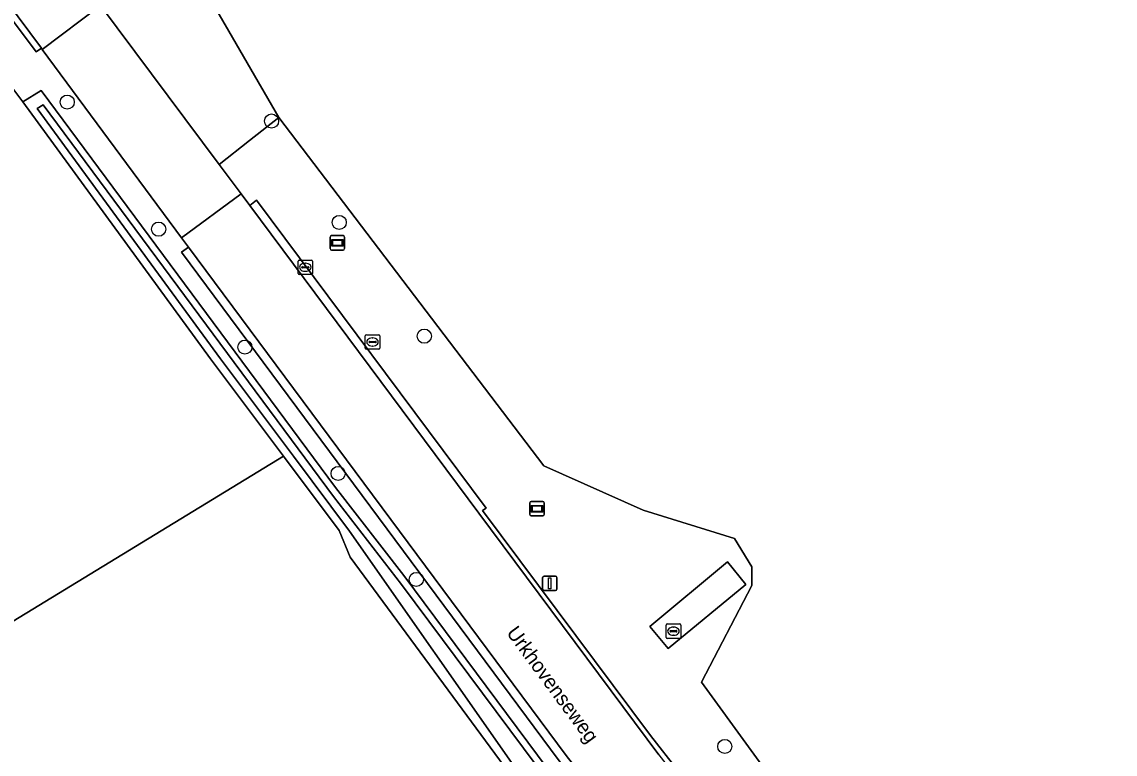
# Model space of a CAD drawing. Extents: x 164494 to 166241, y 382475 to 384495.
# Drawn here: x 165073.2 to 165148.9, y 383082.2 to 383132.9 of the extents above; entities that cross this region are included whole.
import ezdxf

# ---------------------------------------------------------------- set-up
doc = ezdxf.new("R2010")
doc.units = 0
for name, color, linetype in [('IMGEO_Berm_halfverhard', 7, 'Continuous'), ('IMGEO_Boom', 7, 'Continuous'), ('IMGEO_Bouwland', 7, 'Continuous'), ('IMGEO_Brandkraan', 7, 'Continuous'), ('IMGEO_Erf', 7, 'Continuous'), ('IMGEO_Grasland_agrarisch', 7, 'Continuous'), ('IMGEO_Grasland_overig', 7, 'Continuous'), ('IMGEO_Groenvoorziening', 7, 'Continuous'), ('IMGEO_Hek', 7, 'Continuous'), ('IMGEO_Oever', 7, 'Continuous'), ('IMGEO_Openbare_ruimte_label', 7, 'Continuous'), ('IMGEO_Rijbaan_lokaal_gesloten', 7, 'Continuous'), ('IMGEO_Verkeersbordpaal', 7, 'Continuous'), ('IMGEO_Verklikker', 7, 'Continuous'), ('IMGEO_Voetpad_open', 7, 'Continuous'), ('IMGEO_Waterloop', 7, 'Continuous')]:
    doc.layers.add(name, color=color, linetype=linetype)

msp = doc.modelspace()

# ---------------------------------------------------------------- linework, layer by layer
at = {"layer": 'IMGEO_Berm_halfverhard'}
msp.add_lwpolyline([(164958.624, 383286.837), (164958.165, 383286.487), (164958.551, 383285.995), (164958.685, 383286.071), (164960.201, 383284.12), (164981.497, 383255.445), (165004.699, 383224.274), (165010.162, 383216.934), (165012.663, 383213.574), (165041.519, 383174.67), (165059.934, 383149.875), (165074.189, 383130.821), (165074.54, 383131.069), (165010.834, 383216.638), (165007.308, 383221.332), (165004.939, 383224.601), (164967.779, 383274.687)], close=True, dxfattribs=at)
for points in [[(165105.08, 383099.084), (165105.321, 383099.248), (165089.441, 383120.561), (165088.96, 383120.2), (165104.824, 383098.91), (165117.287, 383082.185), (165131.701, 383063.704), (165135.116, 383059.491), (165138.648, 383055.401), (165138.953, 383055.645)], [(165115.42, 383076.3), (165110.865, 383082.129), (165084.718, 383117.313), (165084.231, 383116.963), (165110.383, 383081.771), (165114.948, 383075.929), (165121.14, 383068.038), (165127.167, 383060.515), (165131.174, 383055.545)], [(165132.015, 383063.951), (165116.709, 383083.512), (165105.08, 383099.084)]]:
    msp.add_lwpolyline(points, dxfattribs=at)
at = {"layer": 'IMGEO_Boom'}
for centre in [(165076.331, 383127.349), (165090.474, 383126.038), (165095.156, 383119.022), (165082.657, 383118.554), (165101.044, 383111.15), (165088.626, 383110.392), (165095.079, 383101.648), (165100.493, 383094.313), (165121.84, 383082.758)]:
    msp.add_circle(centre, 0.489, dxfattribs=at)
at = {"layer": 'IMGEO_Bouwland'}
msp.add_lwpolyline([(165074.123, 383155.419), (165090.977, 383126.271), (165109.315, 383102.17), (165116.194, 383099.107), (165122.512, 383097.152), (165123.715, 383095.196), (165123.722, 383093.887), (165120.236, 383087.207), (165137.054, 383064.063), (165140.602, 383063.912), (165142.91, 383065.451), (165147.5, 383063.744), (165151.816, 383066.736), (165153.002, 383067.83), (165157.78, 383071.582), (165165.334, 383076.665), (165168.732, 383079.127), (165168.857, 383079.221), (165175.002, 383083.842)], dxfattribs=at)
at = {"layer": 'IMGEO_Brandkraan'}
for p, q in [((165092.307, 383115.49), (165092.307, 383116.342)), ((165092.382, 383116.416), (165093.234, 383116.416)), ((165092.795, 383116.196), (165092.82, 383116.196)), ((165093.308, 383116.342), (165093.308, 383115.49)), ((165093.234, 383115.416), (165092.382, 383115.416)), ((165092.566, 383115.91), (165092.566, 383115.922)), ((165093.004, 383115.873), (165092.606, 383115.873)), ((165092.609, 383115.959), (165093.007, 383115.959)), ((165092.818, 383115.636), (165092.793, 383115.636)), ((165093.05, 383115.922), (165093.05, 383115.91)), ((165096.96, 383110.32), (165096.96, 383111.172)), ((165097.035, 383111.246), (165097.887, 383111.246)), ((165097.262, 383110.789), (165097.66, 383110.789)), ((165097.448, 383111.026), (165097.473, 383111.026)), ((165097.961, 383111.172), (165097.961, 383110.32)), ((165097.887, 383110.246), (165097.035, 383110.246)), ((165097.219, 383110.74), (165097.219, 383110.752)), ((165097.657, 383110.703), (165097.259, 383110.703)), ((165097.471, 383110.466), (165097.446, 383110.466)), ((165097.703, 383110.752), (165097.703, 383110.74)), ((165117.788, 383090.307), (165117.788, 383091.159)), ((165117.863, 383091.233), (165118.715, 383091.233)), ((165118.789, 383091.159), (165118.789, 383090.307)), ((165118.047, 383090.727), (165118.047, 383090.739)), ((165118.485, 383090.69), (165118.087, 383090.69)), ((165118.09, 383090.776), (165118.488, 383090.776)), ((165118.299, 383090.453), (165118.274, 383090.453)), ((165118.276, 383091.013), (165118.301, 383091.013)), ((165118.531, 383090.739), (165118.531, 383090.727)), ((165118.715, 383090.233), (165117.863, 383090.233))]:
    msp.add_line(p, q, dxfattribs=at)
for points in [[(165092.307, 383115.49), (165092.307, 383116.342)], [(165092.382, 383116.416), (165093.234, 383116.416)], [(165093.308, 383116.342), (165093.308, 383115.49)], [(165093.234, 383115.416), (165092.382, 383115.416)], [(165096.96, 383110.32), (165096.96, 383111.172)], [(165097.035, 383111.246), (165097.887, 383111.246)], [(165097.961, 383111.172), (165097.961, 383110.32)], [(165097.887, 383110.246), (165097.035, 383110.246)], [(165117.788, 383090.307), (165117.788, 383091.159)], [(165117.863, 383091.233), (165118.715, 383091.233)], [(165118.789, 383091.159), (165118.789, 383090.307)], [(165118.715, 383090.233), (165117.863, 383090.233)]]:
    msp.add_lwpolyline(points, dxfattribs=at)
for centre, radius, start, end in [((165092.384, 383116.34), 0.0765, 91.55205, 178.44795), ((165092.384, 383116.34), 0.0765, 91.55205, 178.44795), ((165093.232, 383116.34), 0.0765, 1.55205, 88.44795), ((165093.232, 383116.34), 0.0765, 1.55205, 88.44795), ((165092.384, 383115.492), 0.0765, 181.55205, 268.44795), ((165092.384, 383115.492), 0.0765, 181.55205, 268.44795), ((165092.606, 383115.919), 0.0403, 85.87752, 175.75265), ((165092.603, 383115.909), 0.0366, 178.93798, 274.71019), ((165093.007, 383115.916), 0.043, 264.86636, 352.45326), ((165093.011, 383115.921), 0.0386, 1.73085, 96.63898), ((165093.232, 383115.492), 0.0765, 271.55205, 358.44795), ((165093.232, 383115.492), 0.0765, 271.55205, 358.44795), ((165097.037, 383111.17), 0.0765, 91.55205, 178.44795), ((165097.037, 383111.17), 0.0765, 91.55205, 178.44795), ((165097.259, 383110.749), 0.0403, 85.87752, 175.75265), ((165097.664, 383110.751), 0.0386, 1.73085, 96.63898), ((165097.885, 383111.17), 0.0765, 1.55205, 88.44795), ((165097.885, 383111.17), 0.0765, 1.55205, 88.44795), ((165097.037, 383110.322), 0.0765, 181.55205, 268.44795), ((165097.037, 383110.322), 0.0765, 181.55205, 268.44795), ((165097.256, 383110.739), 0.0366, 178.93798, 274.71019), ((165097.66, 383110.746), 0.043, 264.86636, 352.45326), ((165097.885, 383110.322), 0.0765, 271.55205, 358.44795), ((165097.885, 383110.322), 0.0765, 271.55205, 358.44795), ((165117.865, 383091.157), 0.0765, 91.55205, 178.44795), ((165117.865, 383091.157), 0.0765, 91.55205, 178.44795), ((165118.713, 383091.157), 0.0765, 1.55205, 88.44795), ((165118.713, 383091.157), 0.0765, 1.55205, 88.44795), ((165118.087, 383090.736), 0.0403, 85.87752, 175.75265), ((165118.084, 383090.726), 0.0366, 178.93798, 274.71019), ((165118.488, 383090.733), 0.043, 264.86636, 352.45326), ((165118.492, 383090.738), 0.0386, 1.73085, 96.63898), ((165117.865, 383090.309), 0.0765, 181.55205, 268.44795), ((165117.865, 383090.309), 0.0765, 181.55205, 268.44795), ((165118.713, 383090.309), 0.0765, 271.55205, 358.44795), ((165118.713, 383090.309), 0.0765, 271.55205, 358.44795)]:
    msp.add_arc(centre, radius, start, end, dxfattribs=at)
for centre, major_axis, ratio, start_param, end_param in [((165092.794, 383115.916), (-0.387, 0.002), 0.722429, 4.712389, 7.853982), ((165092.819, 383115.916), (-0.39, 0.002), 0.717154, 1.570796, 4.712389), ((165097.447, 383110.746), (-0.387, 0.002), 0.722429, 4.712389, 7.853982), ((165097.472, 383110.746), (-0.39, 0.002), 0.717154, 1.570796, 4.712389), ((165118.275, 383090.733), (-0.387, 0.002), 0.722429, 4.712389, 7.853982), ((165118.3, 383090.733), (-0.39, 0.002), 0.717154, 1.570796, 4.712389)]:
    msp.add_ellipse(centre, major_axis=major_axis, ratio=ratio, start_param=start_param, end_param=end_param, dxfattribs=at)
at = {"layer": 'IMGEO_Erf'}
msp.add_lwpolyline([(165070.298, 383021.899), (165075.419, 383024.723), (165078.42, 383026.378), (165080.567, 383027.366), (165086.908, 383030.775), (165087.302, 383030.987), (165087.92, 383031.295), (165088.293, 383031.481), (165091.062, 383032.863), (165091.867, 383033.265), (165092.654, 383033.657), (165109.176, 383042.267), (165126.099, 383051.085), (165129.346, 383052.646), (165106.891, 383080.948), (165095.917, 383095.847), (165095.148, 383097.711), (165091.308, 383102.836), (165060.973, 383084.346)], dxfattribs=at)
at = {"layer": 'IMGEO_Grasland_agrarisch'}
msp.add_lwpolyline([(165060.973, 383084.346), (165091.308, 383102.836), (165086.257, 383109.578), (165073.256, 383127.354), (165069.489, 383132.355)], dxfattribs=at)
at = {"layer": 'IMGEO_Grasland_overig'}
for points in [[(165090.977, 383126.271), (165088.95, 383124.679), (165086.849, 383123.029), (165088.367, 383120.996), (165088.96, 383120.2), (165089.441, 383120.561), (165105.321, 383099.248), (165105.08, 383099.084), (165116.709, 383083.512), (165132.015, 383063.951)], [(165175.309, 383081.641), (165173.357, 383080.497), (165169.909, 383077.778), (165168.732, 383079.127), (165165.334, 383076.665), (165166.126, 383075.223), (165158.049, 383069.441), (165154.937, 383067.079), (165152.431, 383065.873), (165151.816, 383066.736), (165147.5, 383063.744), (165142.91, 383065.451), (165140.602, 383063.912), (165137.054, 383064.063), (165120.236, 383087.207), (165123.722, 383093.887), (165123.715, 383095.196), (165122.512, 383097.152), (165116.194, 383099.107), (165109.315, 383102.17), (165090.977, 383126.271)]]:
    msp.add_lwpolyline(points, dxfattribs=at)
msp.add_lwpolyline([(165123.299, 383093.973), (165117.916, 383089.526), (165116.654, 383091.063), (165122.029, 383095.53)], close=True, dxfattribs=at)
at = {"layer": 'IMGEO_Groenvoorziening'}
for points in [[(165131.174, 383055.545), (165127.167, 383060.515), (165121.14, 383068.038), (165114.948, 383075.929), (165110.383, 383081.771), (165084.231, 383116.963), (165084.718, 383117.313), (165084.235, 383117.963), (165074.593, 383130.998), (165074.54, 383131.069), (165074.189, 383130.821), (165059.934, 383149.875), (165041.519, 383174.67), (165012.663, 383213.574), (165010.162, 383216.934)], [(165069.489, 383132.355), (165073.256, 383127.354), (165074.525, 383128.161), (165094.904, 383100.671), (165099.629, 383094.586), (165111.774, 383078.281)]]:
    msp.add_lwpolyline(points, dxfattribs=at)
msp.add_lwpolyline([(165074.123, 383155.419), (165071.264, 383160.363), (165069.136, 383159.073), (165068.351, 383158.548), (165067.377, 383157.726), (165066.958, 383157.262), (165066.406, 383156.474), (165065.993, 383155.616), (165065.827, 383155.087), (165065.758, 383154.474), (165065.68, 383153.791), (165065.74, 383152.848), (165065.842, 383152.183), (165079.122, 383134.381), (165078.641, 383134.022), (165086.849, 383123.029), (165088.95, 383124.679), (165090.977, 383126.271)], close=True, dxfattribs=at)
at = {"layer": 'IMGEO_Hek'}
msp.add_lwpolyline([(165091.308, 383102.836), (165060.973, 383084.346)], dxfattribs=at)
at = {"layer": 'IMGEO_Oever'}
for points in [[(165111.774, 383078.281), (165099.629, 383094.586), (165094.904, 383100.671), (165074.525, 383128.161), (165073.256, 383127.354), (165086.257, 383109.578), (165091.308, 383102.836), (165095.148, 383097.711), (165095.917, 383095.847), (165106.891, 383080.948)], [(165107.563, 383080.96), (165095.862, 383097.667), (165091.983, 383102.844), (165086.934, 383109.584), (165074.261, 383126.911), (165074.656, 383127.161), (165094.75, 383100.055), (165099.476, 383093.969), (165111.62, 383077.665)]]:
    msp.add_lwpolyline(points, dxfattribs=at)
at = {"layer": 'IMGEO_Rijbaan_lokaal_gesloten'}
for points in [[(165010.834, 383216.638), (165074.54, 383131.069), (165074.593, 383130.998), (165078.641, 383134.022)], [(165117.287, 383082.185), (165104.824, 383098.91), (165088.96, 383120.2), (165088.367, 383120.996), (165084.235, 383117.963), (165084.718, 383117.313), (165110.865, 383082.129), (165115.42, 383076.3), (165121.609, 383068.413), (165127.634, 383060.891), (165131.641, 383055.922)]]:
    msp.add_lwpolyline(points, dxfattribs=at)
msp.add_lwpolyline([(165078.641, 383134.022), (165074.593, 383130.998), (165084.235, 383117.963), (165088.367, 383120.996), (165086.849, 383123.029)], close=True, dxfattribs=at)
at = {"layer": 'IMGEO_Verkeersbordpaal'}
for p, q in [((165109.232, 383093.646), (165109.232, 383094.446)), ((165109.232, 383094.446), (165109.232, 383093.646)), ((165109.332, 383094.546), (165110.122, 383094.546)), ((165110.122, 383094.546), (165109.332, 383094.546)), ((165110.222, 383094.446), (165110.222, 383093.646)), ((165110.222, 383093.646), (165110.222, 383094.446)), ((165110.122, 383093.546), (165109.332, 383093.546)), ((165109.332, 383093.546), (165110.122, 383093.546))]:
    msp.add_line(p, q, dxfattribs=at)
msp.add_lwpolyline([(165109.652, 383094.421), (165109.802, 383094.421), (165109.802, 383093.671), (165109.652, 383093.671), (165109.652, 383094.421)], dxfattribs=at)
for centre, start, end in [((165109.332, 383094.446), 90, 180), ((165109.332, 383094.446), 90, 180), ((165110.122, 383094.446), 0, 90), ((165110.122, 383094.446), 360, 90), ((165109.332, 383093.646), 180, 270), ((165109.332, 383093.646), 180, 270), ((165110.122, 383093.646), 270, 0), ((165110.122, 383093.646), 270, 0)]:
    msp.add_arc(centre, 0.1, start, end, dxfattribs=at)
at = {"layer": 'IMGEO_Verklikker'}
for p, q in [((165094.533, 383117.206), (165094.533, 383118.006)), ((165094.533, 383118.006), (165094.533, 383117.206)), ((165094.633, 383118.106), (165095.423, 383118.106)), ((165095.423, 383118.106), (165094.633, 383118.106)), ((165095.523, 383118.006), (165095.523, 383117.206)), ((165095.523, 383117.206), (165095.523, 383118.006)), ((165095.423, 383117.106), (165094.633, 383117.106)), ((165094.633, 383117.106), (165095.423, 383117.106)), ((165108.349, 383098.809), (165108.349, 383099.609)), ((165108.349, 383099.609), (165108.349, 383098.809)), ((165108.449, 383099.709), (165109.239, 383099.709)), ((165109.239, 383099.709), (165108.449, 383099.709)), ((165109.339, 383099.609), (165109.339, 383098.809)), ((165109.339, 383098.809), (165109.339, 383099.609)), ((165109.239, 383098.709), (165108.449, 383098.709)), ((165108.449, 383098.709), (165109.239, 383098.709))]:
    msp.add_line(p, q, dxfattribs=at)
for points in [[(165094.634, 383117.838), (165095.422, 383117.838), (165095.422, 383117.374), (165094.634, 383117.374), (165094.634, 383117.838)], [(165094.699, 383117.773), (165094.699, 383117.439), (165095.357, 383117.439), (165095.357, 383117.773), (165094.699, 383117.773)], [(165108.45, 383099.441), (165109.238, 383099.441), (165109.238, 383098.977), (165108.45, 383098.977), (165108.45, 383099.441)], [(165108.515, 383099.376), (165108.515, 383099.042), (165109.173, 383099.042), (165109.173, 383099.376), (165108.515, 383099.376)]]:
    msp.add_lwpolyline(points, dxfattribs=at)
for centre, start, end in [((165094.633, 383118.006), 90, 180), ((165094.633, 383118.006), 90, 180), ((165095.423, 383118.006), 0, 90), ((165095.423, 383118.006), 360, 90), ((165094.633, 383117.206), 180, 270), ((165094.633, 383117.206), 180, 270), ((165095.423, 383117.206), 270, 0), ((165095.423, 383117.206), 270, 0), ((165108.449, 383099.609), 90, 180), ((165108.449, 383099.609), 90, 180), ((165109.239, 383099.609), 0, 90), ((165109.239, 383099.609), 360, 90), ((165108.449, 383098.809), 180, 270), ((165108.449, 383098.809), 180, 270), ((165109.239, 383098.809), 270, 0), ((165109.239, 383098.809), 270, 0)]:
    msp.add_arc(centre, 0.1, start, end, dxfattribs=at)
at = {"layer": 'IMGEO_Voetpad_open'}
msp.add_lwpolyline([(165123.299, 383093.973), (165122.029, 383095.53), (165116.654, 383091.063), (165117.916, 383089.526)], close=True, dxfattribs=at)
at = {"layer": 'IMGEO_Waterloop'}
msp.add_lwpolyline([(165111.62, 383077.665), (165099.476, 383093.969), (165094.75, 383100.055), (165074.656, 383127.161), (165074.261, 383126.911), (165086.934, 383109.584), (165091.983, 383102.844), (165095.862, 383097.667), (165107.563, 383080.96)], dxfattribs=at)

# ---------------------------------------------------------------- texts
at = {"layer": 'IMGEO_Openbare_ruimte_label'}
msp.add_text('Urkhovenseweg', height=1, rotation=306.37707, dxfattribs=at).set_placement((165106.69, 383090.619))

doc.saveas('drawing.dxf')
